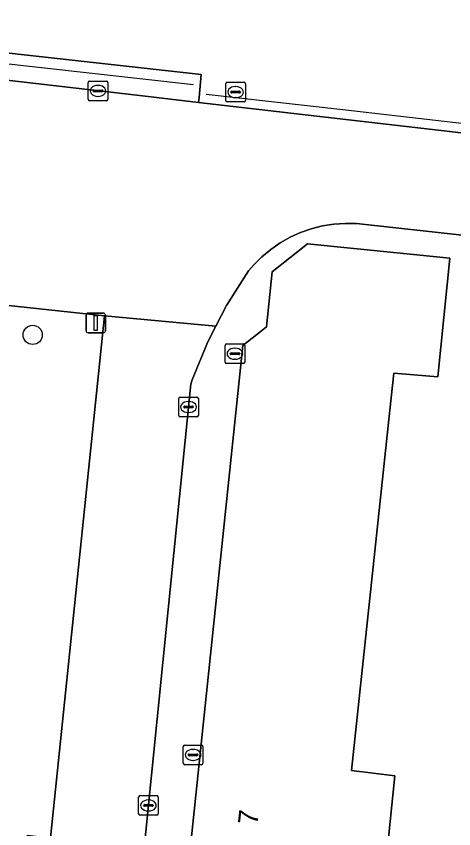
# Model space of a CAD drawing. Extents: x 162510 to 163918, y 388494 to 389774.
# Drawn here: x 162960.88 to 162983.16, y 388666.77 to 388708.17 of the extents above; entities that cross this region are included whole.
import ezdxf

# ---------------------------------------------------------------- set-up
doc = ezdxf.new("R2010")
doc.units = 0
for name, color, linetype in [('IMGEO_Boom', 7, 'Continuous'), ('IMGEO_Groenvoorziening', 7, 'Continuous'), ('IMGEO_Hek', 7, 'Continuous'), ('IMGEO_Kolk', 7, 'Continuous'), ('IMGEO_Lichtmast', 7, 'Continuous'), ('IMGEO_Loofbos', 7, 'Continuous'), ('IMGEO_Pand', 7, 'Continuous'), ('IMGEO_Pand_nummerreeks', 7, 'Continuous'), ('IMGEO_Rioolput', 7, 'Continuous'), ('IMGEO_Voetpad_open', 7, 'Continuous')]:
    doc.layers.add(name, color=color, linetype=linetype)

msp = doc.modelspace()

# ---------------------------------------------------------------- linework, layer by layer
at = {"layer": 'IMGEO_Boom'}
msp.add_circle((162961.715, 388691.936), 0.489, dxfattribs=at)
at = {"layer": 'IMGEO_Groenvoorziening'}
msp.add_lwpolyline([(162943.526, 388708.174), (162963.112, 388705.997), (162970.291, 388705.199), (162970.189, 388704.028), (162970.167, 388703.781), (162987.075, 388701.827)], dxfattribs=at)
at = {"layer": 'IMGEO_Hek'}
for points in [[(162943.832, 388707.61), (162954.409, 388706.43), (162969.911, 388704.701)], [(162970.548, 388704.21), (162977.506, 388703.415), (162988.427, 388702.167), (162989.476, 388702.418), (162991.248, 388702.843), (162992.205, 388703.644), (162993.477, 388704.708), (162994.015, 388705.974), (162994.631, 388707.425)]]:
    msp.add_lwpolyline(points, dxfattribs=at)
at = {"layer": 'IMGEO_Kolk'}
for p, q in [((162964.54, 388703.945), (162964.54, 388704.797)), ((162964.615, 388704.871), (162965.467, 388704.871)), ((162965.028, 388704.651), (162965.053, 388704.651)), ((162965.541, 388704.797), (162965.541, 388703.945)), ((162964.799, 388704.365), (162964.799, 388704.377)), ((162965.237, 388704.328), (162964.839, 388704.328)), ((162964.842, 388704.414), (162965.24, 388704.414)), ((162965.051, 388704.091), (162965.026, 388704.091)), ((162965.283, 388704.377), (162965.283, 388704.365)), ((162965.467, 388703.871), (162964.615, 388703.871)), ((162969.225, 388688.764), (162970.077, 388688.764)), ((162969.15, 388687.838), (162969.15, 388688.69)), ((162969.638, 388688.544), (162969.663, 388688.544)), ((162970.151, 388688.69), (162970.151, 388687.838)), ((162969.409, 388688.258), (162969.409, 388688.27)), ((162969.847, 388688.221), (162969.449, 388688.221)), ((162969.452, 388688.307), (162969.85, 388688.307)), ((162969.661, 388687.984), (162969.636, 388687.984)), ((162969.893, 388688.27), (162969.893, 388688.258)), ((162970.077, 388687.764), (162969.225, 388687.764)), ((162967.183, 388668.46), (162968.035, 388668.46)), ((162967.108, 388667.534), (162967.108, 388668.386)), ((162967.596, 388668.24), (162967.621, 388668.24)), ((162968.109, 388668.386), (162968.109, 388667.534)), ((162967.367, 388667.954), (162967.367, 388667.966)), ((162967.805, 388667.917), (162967.407, 388667.917)), ((162967.41, 388668.003), (162967.808, 388668.003)), ((162967.619, 388667.68), (162967.594, 388667.68)), ((162967.851, 388667.966), (162967.851, 388667.954)), ((162968.035, 388667.46), (162967.183, 388667.46))]:
    msp.add_line(p, q, dxfattribs=at)
for points in [[(162964.54, 388703.945), (162964.54, 388704.797)], [(162964.615, 388704.871), (162965.467, 388704.871)], [(162965.541, 388704.797), (162965.541, 388703.945)], [(162965.467, 388703.871), (162964.615, 388703.871)], [(162969.225, 388688.764), (162970.077, 388688.764)], [(162969.15, 388687.838), (162969.15, 388688.69)], [(162970.151, 388688.69), (162970.151, 388687.838)], [(162970.077, 388687.764), (162969.225, 388687.764)], [(162967.183, 388668.46), (162968.035, 388668.46)], [(162967.108, 388667.534), (162967.108, 388668.386)], [(162968.109, 388668.386), (162968.109, 388667.534)], [(162968.035, 388667.46), (162967.183, 388667.46)]]:
    msp.add_lwpolyline(points, dxfattribs=at)
for centre, radius, start, end in [((162964.617, 388704.795), 0.0765, 91.552, 178.448), ((162964.617, 388704.795), 0.0765, 91.552, 178.448), ((162965.465, 388704.795), 0.0765, 1.552, 88.448), ((162965.465, 388704.795), 0.0765, 1.552, 88.448), ((162964.839, 388704.374), 0.0403, 85.8775, 175.7526), ((162964.836, 388704.364), 0.0366, 178.938, 274.7102), ((162965.24, 388704.371), 0.043, 264.8664, 352.4533), ((162965.244, 388704.376), 0.0386, 1.7309, 96.639), ((162964.617, 388703.947), 0.0765, 181.552, 268.448), ((162964.617, 388703.947), 0.0765, 181.552, 268.448), ((162965.465, 388703.947), 0.0765, 271.552, 358.448), ((162965.465, 388703.947), 0.0765, 271.552, 358.448), ((162969.227, 388688.688), 0.0765, 91.552, 178.448), ((162969.227, 388688.688), 0.0765, 91.552, 178.448), ((162970.075, 388688.688), 0.0765, 1.552, 88.448), ((162970.075, 388688.688), 0.0765, 1.552, 88.448), ((162969.449, 388688.267), 0.0403, 85.8775, 175.7526), ((162969.446, 388688.257), 0.0366, 178.938, 274.7102), ((162969.85, 388688.264), 0.043, 264.8664, 352.4533), ((162969.854, 388688.269), 0.0386, 1.7309, 96.639), ((162969.227, 388687.84), 0.0765, 181.552, 268.448), ((162969.227, 388687.84), 0.0765, 181.552, 268.448), ((162970.075, 388687.84), 0.0765, 271.552, 358.448), ((162970.075, 388687.84), 0.0765, 271.552, 358.448), ((162967.185, 388668.384), 0.0765, 91.552, 178.448), ((162967.185, 388668.384), 0.0765, 91.552, 178.448), ((162968.033, 388668.384), 0.0765, 1.552, 88.448), ((162968.033, 388668.384), 0.0765, 1.552, 88.448), ((162967.407, 388667.963), 0.0403, 85.8775, 175.7526), ((162967.404, 388667.953), 0.0366, 178.938, 274.7102), ((162967.808, 388667.96), 0.043, 264.8664, 352.4533), ((162967.812, 388667.965), 0.0386, 1.7309, 96.639), ((162967.185, 388667.536), 0.0765, 181.552, 268.448), ((162967.185, 388667.536), 0.0765, 181.552, 268.448), ((162968.033, 388667.536), 0.0765, 271.552, 358.448), ((162968.033, 388667.536), 0.0765, 271.552, 358.448)]:
    msp.add_arc(centre, radius, start, end, dxfattribs=at)
for centre, major_axis, ratio, start_param, end_param in [((162965.027, 388704.371), (-0.387, 0.002), 0.722429, 4.712389, 7.853982), ((162965.052, 388704.371), (-0.39, 0.002), 0.717154, 1.570796, 4.712389), ((162969.637, 388688.264), (-0.387, 0.002), 0.722429, 4.712389, 7.853982), ((162969.662, 388688.264), (-0.39, 0.002), 0.717154, 1.570796, 4.712389), ((162967.595, 388667.96), (-0.387, 0.002), 0.722429, 4.712389, 7.853982), ((162967.62, 388667.96), (-0.39, 0.002), 0.717154, 1.570796, 4.712389)]:
    msp.add_ellipse(centre, major_axis=major_axis, ratio=ratio, start_param=start_param, end_param=end_param, dxfattribs=at)
at = {"layer": 'IMGEO_Lichtmast'}
for p, q in [((162964.431, 388692.144), (162964.431, 388692.944)), ((162964.431, 388692.944), (162964.431, 388692.144)), ((162964.531, 388693.044), (162965.321, 388693.044)), ((162965.321, 388693.044), (162964.531, 388693.044)), ((162965.421, 388692.944), (162965.421, 388692.144)), ((162965.421, 388692.144), (162965.421, 388692.944)), ((162965.321, 388692.044), (162964.531, 388692.044)), ((162964.531, 388692.044), (162965.321, 388692.044))]:
    msp.add_line(p, q, dxfattribs=at)
msp.add_lwpolyline([(162964.851, 388692.919), (162965.001, 388692.919), (162965.001, 388692.169), (162964.851, 388692.169), (162964.851, 388692.919)], dxfattribs=at)
for centre, start, end in [((162964.531, 388692.944), 90, 180), ((162964.531, 388692.944), 90, 180), ((162965.321, 388692.944), 0, 90), ((162965.321, 388692.944), 360, 90), ((162964.531, 388692.144), 180, 270), ((162964.531, 388692.144), 180, 270), ((162965.321, 388692.144), 270, 0), ((162965.321, 388692.144), 270, 0)]:
    msp.add_arc(centre, 0.1, start, end, dxfattribs=at)
at = {"layer": 'IMGEO_Loofbos'}
msp.add_lwpolyline([(162962.318, 388663.417), (162961.127, 388663.557), (162961.448, 388666.446), (162962.617, 388666.303), (162965.366, 388692.914), (162958.574, 388693.639), (162957.885, 388686.768), (162950.722, 388623.179), (162955.017, 388622.601), (162958.059, 388622.192)], close=True, dxfattribs=at)
at = {"layer": 'IMGEO_Pand'}
msp.add_lwpolyline([(162973.983, 388641.944), (162974.212, 388642.129), (162979.834, 388646.664), (162978.034, 388648.858), (162979.202, 388660.172), (162979.757, 388660.621), (162979.315, 388661.183), (162979.532, 388663.147), (162980.058, 388663.595), (162979.616, 388664.152), (162980.165, 388669.466), (162977.948, 388669.744), (162979.9, 388688.105), (162980.1, 388689.993), (162982.355, 388689.801), (162982.959, 388695.844), (162975.704, 388696.571), (162973.91, 388695.143), (162973.619, 388692.348), (162973.366, 388692.148), (162972.414, 388691.394), (162967.425, 388643.61), (162973.11, 388643.02)], close=True, dxfattribs=at)
at = {"layer": 'IMGEO_Rioolput'}
for p, q in [((162971.55, 388703.883), (162971.55, 388704.735)), ((162971.625, 388704.809), (162972.477, 388704.809)), ((162972.038, 388704.589), (162972.063, 388704.589)), ((162972.551, 388704.735), (162972.551, 388703.883)), ((162971.809, 388704.303), (162971.809, 388704.315)), ((162972.247, 388704.266), (162971.849, 388704.266)), ((162971.852, 388704.352), (162972.25, 388704.352)), ((162972.293, 388704.315), (162972.293, 388704.303)), ((162972.477, 388703.809), (162971.625, 388703.809)), ((162972.061, 388704.029), (162972.036, 388704.029)), ((162971.513, 388690.552), (162971.513, 388691.404)), ((162971.588, 388691.478), (162972.44, 388691.478)), ((162972.001, 388691.258), (162972.026, 388691.258)), ((162972.514, 388691.404), (162972.514, 388690.552)), ((162971.772, 388690.972), (162971.772, 388690.984)), ((162972.21, 388690.935), (162971.812, 388690.935)), ((162971.815, 388691.021), (162972.213, 388691.021)), ((162972.256, 388690.984), (162972.256, 388690.972)), ((162972.44, 388690.478), (162971.588, 388690.478)), ((162972.024, 388690.698), (162971.999, 388690.698)), ((162969.381, 388670.11), (162969.381, 388670.962)), ((162969.456, 388671.036), (162970.308, 388671.036)), ((162970.382, 388670.962), (162970.382, 388670.11)), ((162969.64, 388670.53), (162969.64, 388670.542)), ((162969.683, 388670.579), (162970.081, 388670.579)), ((162969.869, 388670.816), (162969.894, 388670.816)), ((162970.124, 388670.542), (162970.124, 388670.53)), ((162970.078, 388670.493), (162969.68, 388670.493)), ((162969.892, 388670.256), (162969.867, 388670.256)), ((162970.308, 388670.036), (162969.456, 388670.036))]:
    msp.add_line(p, q, dxfattribs=at)
for points in [[(162971.55, 388703.883), (162971.55, 388704.735)], [(162971.625, 388704.809), (162972.477, 388704.809)], [(162972.551, 388704.735), (162972.551, 388703.883)], [(162972.477, 388703.809), (162971.625, 388703.809)], [(162971.513, 388690.552), (162971.513, 388691.404)], [(162971.588, 388691.478), (162972.44, 388691.478)], [(162972.514, 388691.404), (162972.514, 388690.552)], [(162972.44, 388690.478), (162971.588, 388690.478)], [(162969.381, 388670.11), (162969.381, 388670.962)], [(162969.456, 388671.036), (162970.308, 388671.036)], [(162970.382, 388670.962), (162970.382, 388670.11)], [(162970.308, 388670.036), (162969.456, 388670.036)]]:
    msp.add_lwpolyline(points, dxfattribs=at)
for centre, radius, start, end in [((162971.627, 388704.733), 0.0765, 91.552, 178.448), ((162971.627, 388704.733), 0.0765, 91.552, 178.448), ((162972.475, 388704.733), 0.0765, 1.552, 88.448), ((162972.475, 388704.733), 0.0765, 1.552, 88.448), ((162971.849, 388704.312), 0.0403, 85.8775, 175.7526), ((162971.846, 388704.302), 0.0366, 178.938, 274.7102), ((162972.25, 388704.309), 0.043, 264.8664, 352.4533), ((162972.254, 388704.314), 0.0386, 1.7309, 96.639), ((162971.627, 388703.885), 0.0765, 181.552, 268.448), ((162971.627, 388703.885), 0.0765, 181.552, 268.448), ((162972.475, 388703.885), 0.0765, 271.552, 358.448), ((162972.475, 388703.885), 0.0765, 271.552, 358.448), ((162971.59, 388691.402), 0.0765, 91.552, 178.448), ((162971.59, 388691.402), 0.0765, 91.552, 178.448), ((162972.438, 388691.402), 0.0765, 1.552, 88.448), ((162972.438, 388691.402), 0.0765, 1.552, 88.448), ((162971.812, 388690.981), 0.0403, 85.8775, 175.7526), ((162971.809, 388690.971), 0.0366, 178.938, 274.7102), ((162972.213, 388690.978), 0.043, 264.8664, 352.4533), ((162972.217, 388690.983), 0.0386, 1.7309, 96.639), ((162971.59, 388690.554), 0.0765, 181.552, 268.448), ((162971.59, 388690.554), 0.0765, 181.552, 268.448), ((162972.438, 388690.554), 0.0765, 271.552, 358.448), ((162972.438, 388690.554), 0.0765, 271.552, 358.448), ((162969.458, 388670.96), 0.0765, 91.552, 178.448), ((162969.458, 388670.96), 0.0765, 91.552, 178.448), ((162970.306, 388670.96), 0.0765, 1.552, 88.448), ((162970.306, 388670.96), 0.0765, 1.552, 88.448), ((162969.68, 388670.539), 0.0403, 85.8775, 175.7526), ((162969.677, 388670.529), 0.0366, 178.938, 274.7102), ((162970.081, 388670.536), 0.043, 264.8664, 352.4533), ((162970.085, 388670.541), 0.0386, 1.7309, 96.639), ((162969.458, 388670.112), 0.0765, 181.552, 268.448), ((162969.458, 388670.112), 0.0765, 181.552, 268.448), ((162970.306, 388670.112), 0.0765, 271.552, 358.448), ((162970.306, 388670.112), 0.0765, 271.552, 358.448)]:
    msp.add_arc(centre, radius, start, end, dxfattribs=at)
for centre, major_axis, ratio, start_param, end_param in [((162972.037, 388704.309), (-0.387, 0.002), 0.722429, 4.712389, 7.853982), ((162972.062, 388704.309), (-0.39, 0.002), 0.717154, 1.570796, 4.712389), ((162972, 388690.978), (-0.387, 0.002), 0.722429, 4.712389, 7.853982), ((162972.025, 388690.978), (-0.39, 0.002), 0.717154, 1.570796, 4.712389), ((162969.868, 388670.536), (-0.387, 0.002), 0.722429, 4.712389, 7.853982), ((162969.893, 388670.536), (-0.39, 0.002), 0.717154, 1.570796, 4.712389)]:
    msp.add_ellipse(centre, major_axis=major_axis, ratio=ratio, start_param=start_param, end_param=end_param, dxfattribs=at)
at = {"layer": 'IMGEO_Voetpad_open'}
for points in [[(162943.308, 388706.87), (162946.434, 388706.523), (162967.307, 388704.111), (162970.167, 388703.781), (162970.189, 388704.028), (162970.291, 388705.199), (162963.112, 388705.997), (162943.526, 388708.174)], [(162969.769, 388689.43), (162969.843, 388689.64), (162970.632, 388691.577), (162971.049, 388692.387), (162965.366, 388692.914), (162962.617, 388666.303), (162962.318, 388663.417), (162958.059, 388622.192), (162957.848, 388620.153), (162957.755, 388619.254), (162962.649, 388618.722), (162963.647, 388628.636), (162963.767, 388629.826), (162963.893, 388631.072), (162965.179, 388643.845)]]:
    msp.add_lwpolyline(points, close=True, dxfattribs=at)
for points in [[(162987.075, 388701.827), (162970.167, 388703.781), (162967.307, 388704.111), (162946.434, 388706.523)], [(162958.574, 388693.639), (162965.366, 388692.914), (162971.049, 388692.387), (162971.59, 388693.436), (162972.711, 388695.202), (162972.976, 388695.509), (162973.389, 388695.92), (162973.837, 388696.293), (162974.316, 388696.624), (162974.824, 388696.912), (162975.355, 388697.152), (162975.905, 388697.345), (162976.471, 388697.487), (162977.046, 388697.578), (162977.628, 388697.618), (162978.211, 388697.605), (162988.836, 388696.441)], [(162988.836, 388696.441), (162978.211, 388697.605), (162977.628, 388697.618), (162977.046, 388697.578), (162976.471, 388697.487), (162975.905, 388697.345), (162975.355, 388697.152), (162974.824, 388696.912), (162974.316, 388696.624), (162973.837, 388696.293), (162973.389, 388695.92), (162972.976, 388695.509), (162972.711, 388695.202), (162971.59, 388693.436), (162971.049, 388692.387), (162970.632, 388691.577), (162969.843, 388689.64), (162969.769, 388689.43), (162965.179, 388643.845)], [(162967.425, 388643.61), (162972.414, 388691.394), (162973.366, 388692.148), (162973.619, 388692.348), (162973.91, 388695.143), (162975.704, 388696.571), (162982.959, 388695.844), (162982.355, 388689.801), (162980.1, 388689.993), (162979.9, 388688.105), (162977.948, 388669.744), (162980.165, 388669.466), (162979.616, 388664.152)]]:
    msp.add_lwpolyline(points, dxfattribs=at)

# ---------------------------------------------------------------- texts
at = {"layer": 'IMGEO_Pand_nummerreeks'}
msp.add_text('7', height=1, rotation=84.0424, dxfattribs=at).set_placement((162973.157, 388666.938))

doc.saveas('drawing.dxf')
